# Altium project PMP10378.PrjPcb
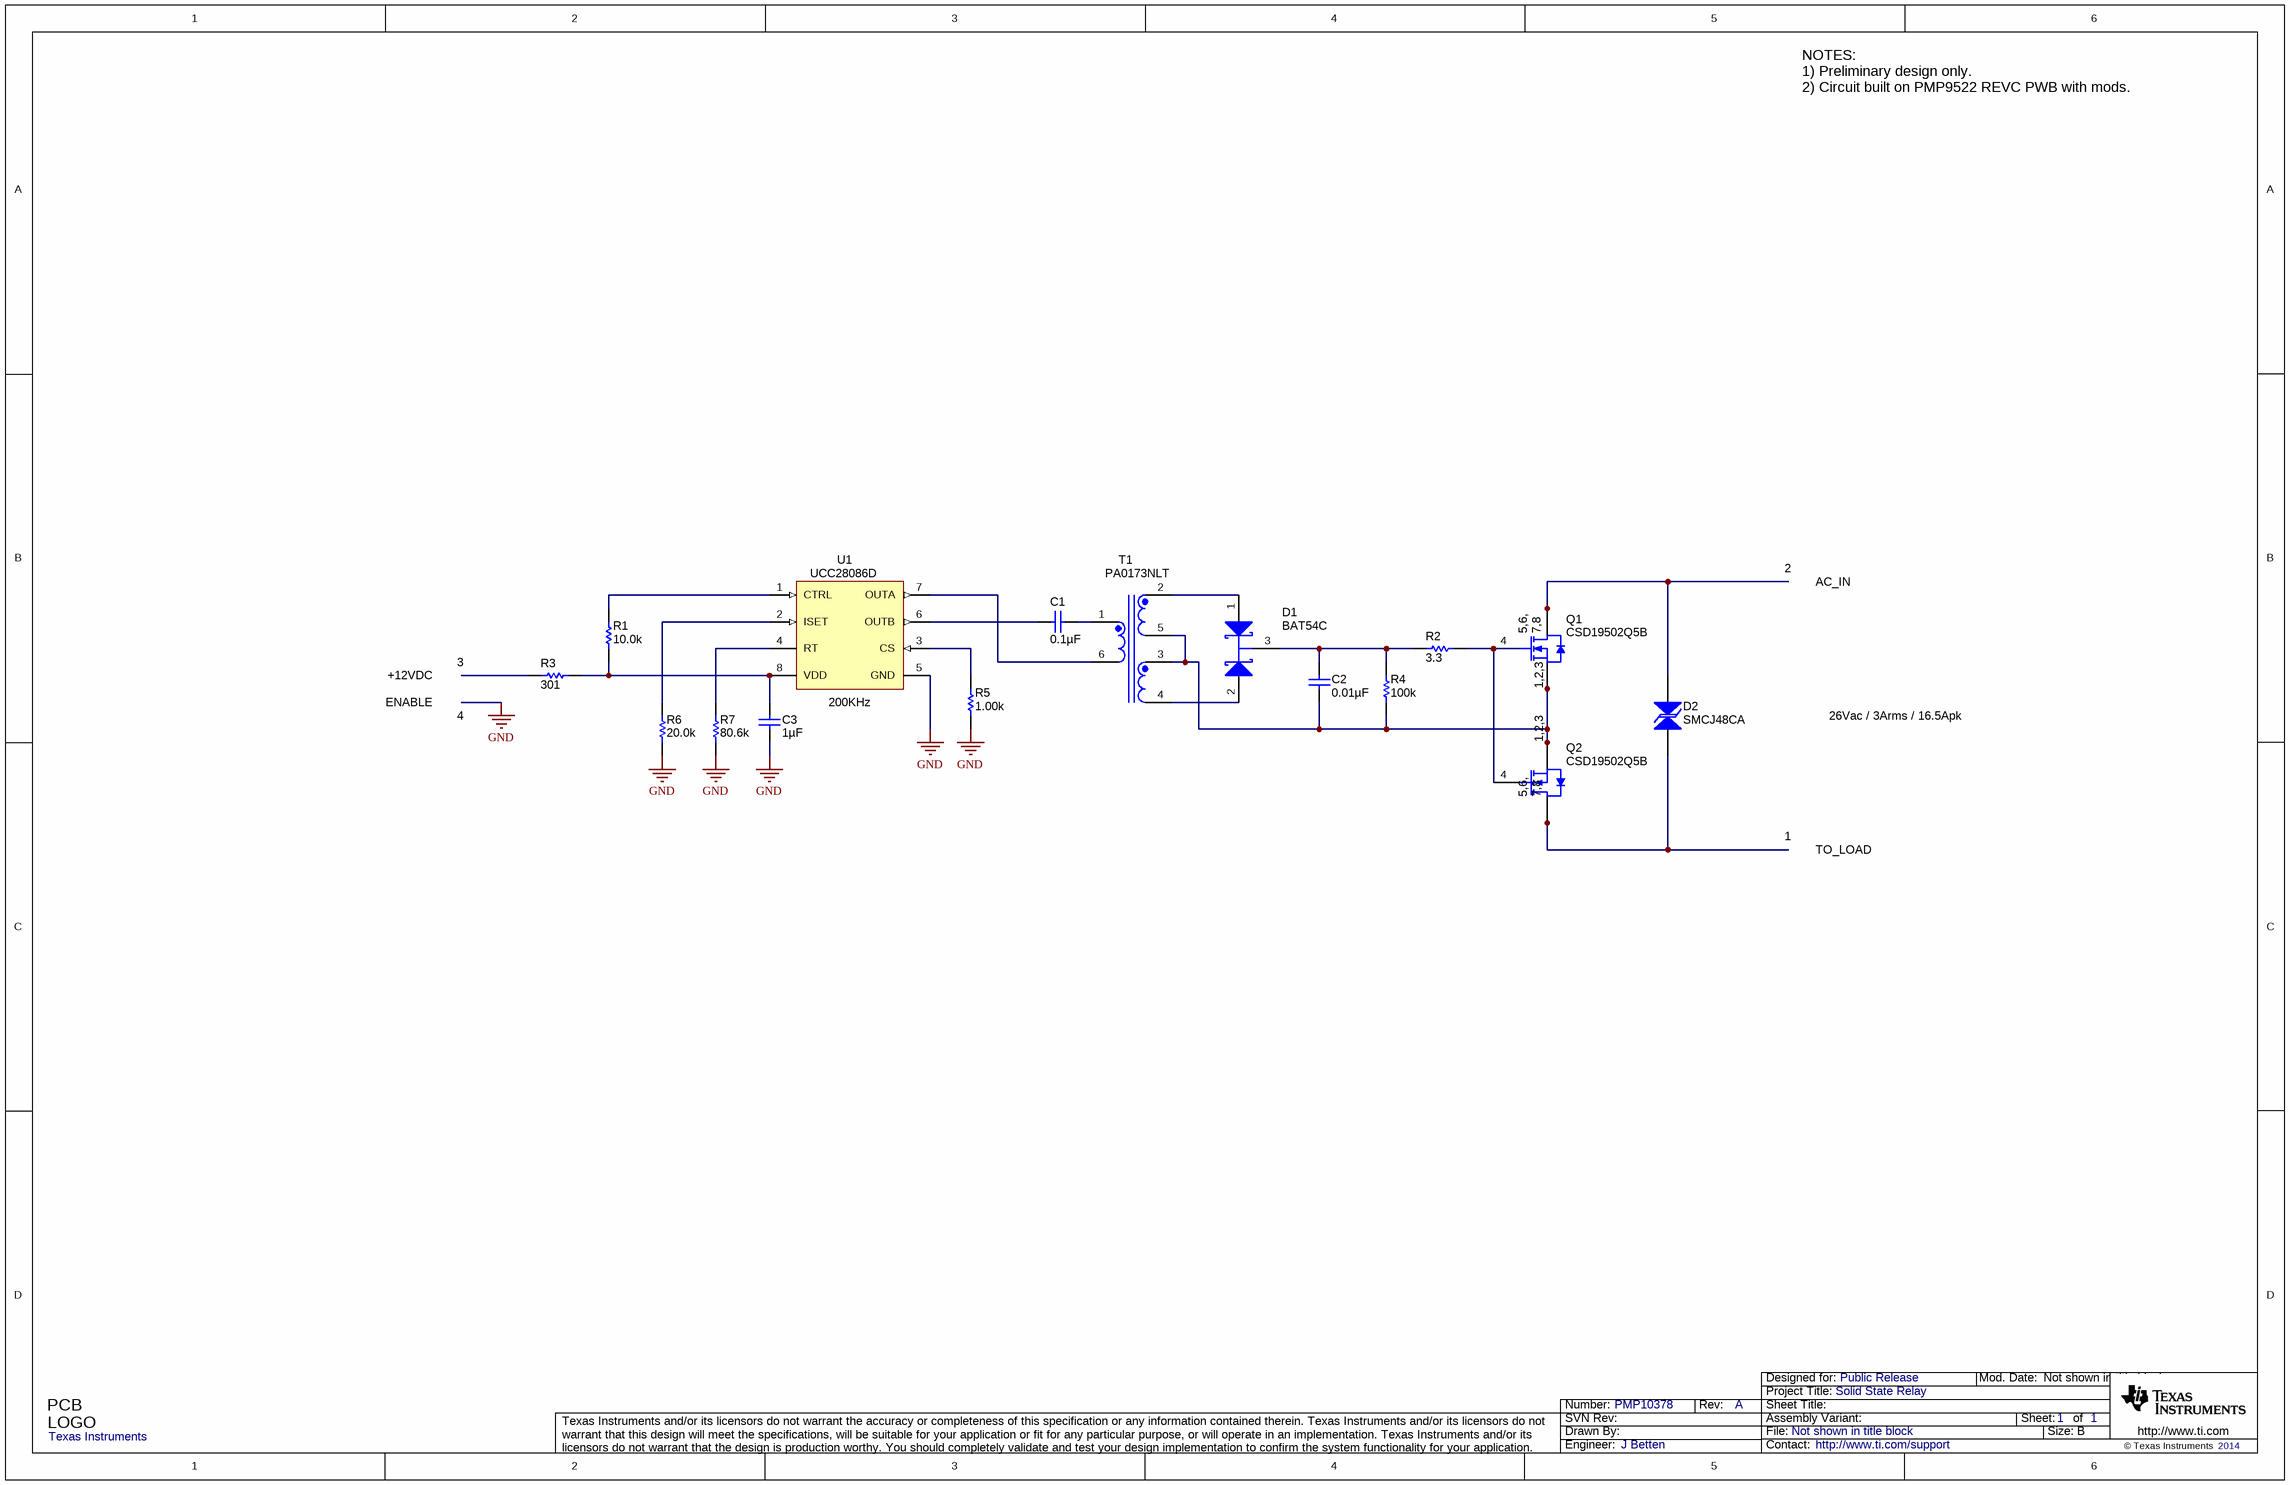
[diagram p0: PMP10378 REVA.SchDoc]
TechSupport: http://www.ti.com/support; SCH_Rev: A; PRJ_Title: Solid State Relay; PRJ_Number: PMP10378; PRJ_Engineer: J Betten; PRJ_Customer: Public Release; PCB_Rev: A; PCB_Layout: J Betten; CopyrightYear: 2014
1 sheet, 17 parts. Net scope: global (net labels, ports and power ports of the same name join across sheets).
Board file: PMP10378 REVA.PcbDoc

## Sheet PMP10378 REVA.SchDoc
size 431 x 279 mm; Date: Not shown in title block; ApprovedBy: Not shown in title block; CheckedBy: Not shown in title block; Author: Not shown in title block; CompanyName: Not shown in title block; Engineer: Not shown in title block; Organization: Not shown in title block; Address1: Not shown in title block; Address2: Not shown in title block; Address3: Not shown in title block; Address4: Not shown in title block; DocumentNumber: 1; Revision: Use project parameter SCH_Rev; SheetNumber: 1; SheetTotal: 1; PageSetup: Record=PageOptions¦CenterHorizontal=True¦CenterVertical=True¦PrintScale=1.00¦XCorrection=1.00¦YCorrection=1.00¦PrintKind=0¦BorderSize=5000000¦LeftOffset=0¦BottomOffset=0¦Orientation=2¦PaperLength=1000¦PaperWidth=1000¦Scale=100¦PaperSource=15¦PrintQuality=600¦MediaType=1¦DitherType=10¦PaperKind=Letter¦PrintScaleMode=1

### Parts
C1  ValueDisplayed: 0.1µF  [0603]  (hidden comment: C1608X7R1H104K)
C2  ValueDisplayed: 0.01µF  [0603]  (hidden comment: C1608X7R1H103K)
C3  ValueDisplayed: 1µF  [0603]  (hidden comment: C1608X5R1C105K)
D1  BAT54C  [SOT-23]
D2  SMCJ48CA  [SMC]
Logo1  Texas Instruments  [TI_Stacked_Overlay_Small]  (no BOM)
Q1  CSD19502Q5B  [TRANS_NexFET_Q5B]
Q2  CSD19502Q5B  [TRANS_NexFET_Q5B]
R1  ValueDisplayed: 10.0k  [0603]  (hidden comment: CRCW060310K0FKEA)
R2  value 3.3  [0603]  (hidden comment: CRCW06033R30JNEA)
R3  value 301  [0805_HV]  (hidden comment: CRCW0805301RFKEA)
R4  value 100k  [0603]  (hidden comment: CRCW0603100KFKEA)
R5  ValueDisplayed: 1.00k  [0603]  (hidden comment: CRCW06031K00FKEA)
R6  ValueDisplayed: 20.0k  [0603]  (hidden comment: CRCW060320K0FKEA)
R7  ValueDisplayed: 80.6k  [0603]  (hidden comment: CRCW060380K6FKEA)
T1  PA0173NLT  [PULSE_PA0173]
U1  UCC28086D  [D0008A_N]

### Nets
GND: C3.1 R5.2 R6.2 R7.2 U1.5(GND)
NetC1_1: C1.1 U1.6(OUTB)
NetC1_2: C1.2 T1.1
NetC2_1: C2.1 D1.3(K) R2.2 R4.2
NetC2_2: C2.2 Q1.1(S) Q1.2(S) Q1.3(S) Q2.1(S) Q2.2(S) Q2.3(S) R4.1 T1.3 T1.5
NetC3_2: C3.2 R1.2 R3.2 U1.8(VDD)
NetD1_1: D1.1(A1) T1.2
NetD1_2: D1.2(A2) T1.4
NetD2_1: D2.1 Q1.5(D) Q1.6(D) Q1.7(D) Q1.8(D)
NetD2_2: D2.2 Q2.5(D) Q2.6(D) Q2.7(D) Q2.8(D)
NetQ1_4: Q1.4(G) Q2.4(G) R2.1
NetR1_1: R1.1 U1.1(CTRL)
NetR5_1: R5.1 U1.3(CS)
NetR6_1: R6.1 U1.2(ISET)
NetR7_1: R7.1 U1.4(RT)
NetT1_6: T1.6 U1.7(OUTA)

Not connected (* = marked no-connect by the designer): R3 1

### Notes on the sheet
- NOTES:
  1) Preliminary design only.
  2) Circuit built on PMP9522 REVC PWB with mods.
- 2
- AC_IN
- ENABLE
- +12VDC
- 3
- (near U1) 200KHz
- 4
- 26Vac / 3Arms / 16.5Apk
- 1
- TO_LOAD

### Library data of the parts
C1 = C1608X7R1H104K: CAP, CERM, 0.1uF, 50V, +/-10%, X7R, 0603; Manufacturer: TDK; Polarized: N; CompType: Capacitor; U/M: EA; Cap_F: 0.0000001; Tolerance_%: 10; ESR_Ohm: 0.017; Value1: 0.017 ohm; VDC_V: 50; TaMin_C: -55; TaMax_C: 125
C2 = C1608X7R1H103K: CAP, CERM, 0.01uF, 50V, +/-10%, X7R, 0603; Manufacturer: TDK; Polarized: N; CompType: Capacitor; U/M: EA; Cap_F: 0.00000001; Tolerance_%: 10; ESR_Ohm: 0.0539; Value1: 0.0539 ohm; VDC_V: 50; TaMin_C: -55; TaMax_C: 125
C3 = C1608X5R1C105K: CAP, CERM, 1uF, 16V, +/-10%, X5R, 0603; Manufacturer: TDK; Polarized: N; CompType: Capacitor; U/M: EA; Cap_F: 0.000001; Tolerance_%: 10; ESR_Ohm: 0.0057; Value1: 0.0057 ohm; VDC_V: 16; TaMin_C: -55; TaMax_C: 85
D1 = BAT54C-7-F: Diode, Schottky, 30V, 0.2A, SOT-23; Manufacturer: Diodes Inc.; U/M: EA; Vf_V: 0.65; Value2: 0.65V; Io_A: 0.2; Vr_V: 30; TJmax_C: 125
D2 = SMCJ33CA: Diode, TVS, Bi, 48V, 1500W, SMC; Manufacturer: Bourns; U/M: EA; Power_W: 1500; Vr_V: 48
Logo1 = TI_Logo: Texas Instrument Corporate Signature; SymbolCreator: a0412235
Q1 Q2 = CSD18532Q5B: MOSFET, N-CH, 80V, 3.4 mOhms, SON 5x6mm; Manufacturer: Texas Instruments; Alternate Manufacturer: None; U/M: EA; ChType: N; VdsMax_V: 80; Value1: 3.5 milliohm; Rdson45_Ohm: 3.3; Value2: 48nC; QgTyp_nC: 27; IdsMax_A: 172
R1 = CRCW060310K0FKEA: RES, 10.0 k, 1%, 0.1 W, 0603; Manufacturer: Vishay-Dale; CompType: Resistor; Value: 10.0k; Res_ohm: 10000; Value_Code: 10k0; Tolerance_%: 1; Power_W: 0.1; Value2: 0.1W; VDC_V: 75; TempCo: 100 ppm/C; EIA_Code: E96; U/M: EA
R2 = CRCW06033R30JNEA: RES, 3.3 ohm, 5%, 0.1W, 0603; Manufacturer: Vishay-Dale; CompType: Resistor; Value_Code: 3R30; Tolerance_%: 5; Power_W: 0.1; VDC_V: 75; TempCo: 200 ppm/C; EIA_Code: E24; U/M: EA
R3 = CRCW0805301RFKEA: RES, 301 ohm, 1%, 0.125W, 0805; Manufacturer: Vishay-Dale; CompType: Resistor; Value_Code: 301R; Tolerance_%: 1; Power_W: 0.125; VDC_V: 150; TempCo: 100 ppm/C; EIA_Code: E96; U/M: EA
R4 = CRCW0603100KFKEA: RES, 100k ohm, 1%, 0.1W, 0603; Manufacturer: Vishay-Dale; CompType: Resistor; Res_ohm: 100000; Tolerance_%: 1; Power_W: 0.1; VDC_V: 75; TempCo: 100 ppm/C; EIA_Code: E96; U/M: EA
R5 = CRCW06031K00FKEA: RES, 1.00 k, 1%, 0.1 W, 0603; Manufacturer: Vishay-Dale; CompType: Resistor; Value: 1.00k; Res_ohm: 1000; Value_Code: 1k00; Tolerance_%: 1; Power_W: 0.1; Value2: 0.1W; VDC_V: 75; TempCo: 100 ppm/C; EIA_Code: E96; U/M: EA
R6 = CRCW060320K0FKEA: RES, 20.0 k, 1%, 0.1 W, 0603; Manufacturer: Vishay-Dale; CompType: Resistor; Value: 20.0k; Res_ohm: 20000; Value_Code: 20k0; Tolerance_%: 1; Power_W: 0.1; Value2: 0.1W; VDC_V: 75; TempCo: 100 ppm/C; EIA_Code: E96; U/M: EA
R7 = CRCW060380K6FKEA: RES, 80.6 k, 1%, 0.1 W, 0603; Manufacturer: Vishay-Dale; CompType: Resistor; Value: 80.6k; Res_ohm: 80600; Value_Code: 80k6; Tolerance_%: 1; Power_W: 0.1; Value2: 0.1W; VDC_V: 75; TempCo: 100 ppm/C; EIA_Code: E96; U/M: EA
T1 = PA0173NLT: Transformer, Gate Drive, 980uH, SMT; Manufacturer: Pulse Engineering; SymbolCreator: a0411947; DCR_Ohm: 0.62; LeakageL: 0.75uH; U/M: EA
U1 = UCC28086D: Push-Pull PWM Controller with Programmable Slope Compensation with Current Control, 50 % Duty Cycle, -40 to +85 degC, 8-pin SOIC (D), Green (RoHS & no Sb/Br); Manufacturer: Texas Instruments; Alternate Manufacturer: None; Alternate PartNumber: Equivalent; Duty Cycle(Max)(%): 50; Frequency(Max)(kHz): 1000; Rating: Catalog; Regulated Outputs(#): 2; Topology: Half-Bridge, Push-Pull; UVLO Thresholds On/Off(V): 4.3/4.1

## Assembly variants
001: not fitted FID1 FID2 FID3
